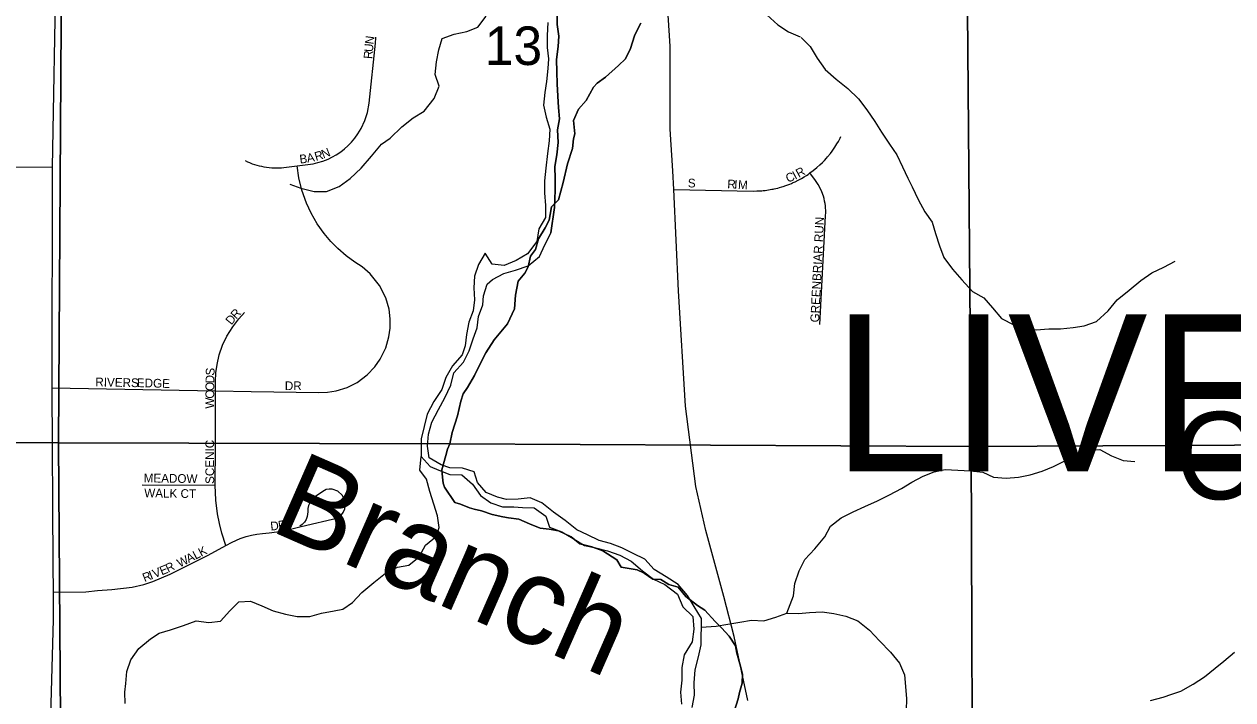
# Model space of a CAD drawing. Extents: x 1985906 to 2277390, y 930619 to 1324581.
# Drawn here: x 2123724 to 2130652, y 1175711 to 1179583 of the extents above; entities that cross this region are included whole.
import ezdxf

# ---------------------------------------------------------------- set-up
doc = ezdxf.new("R2010")
doc.units = 0
for name, color, linetype in [('GM_X_County_Road', 7, 'Continuous'), ('GM_X_Major_River', 7, 'Continuous'), ('GM_X_Major_River_Text', 7, 'Continuous'), ('GM_X_Minor_River', 7, 'Continuous'), ('GM_X_Minor_River_Text', 7, 'Continuous'), ('GM_X_Section', 7, 'Continuous'), ('GM_X_Section_Text', 7, 'Continuous'), ('GM_X_State_Route', 7, 'Continuous'), ('GM_X_Township_Subdivision', 7, 'Continuous'), ('GM_X_Township_Subdivision_Text', 7, 'Continuous'), ('GM_X_Township_Text', 7, 'Continuous')]:
    doc.layers.add(name, color=color, linetype=linetype)

msp = doc.modelspace()

# ---------------------------------------------------------------- linework, layer by layer
at = {"layer": 'GM_X_County_Road'}
msp.add_lwpolyline([(2123773.2, 1166122.9), (2123795.2, 1166134.3), (2123816, 1166178.8), (2123824.9, 1166242.7), (2123823.4, 1166364.4), (2123796, 1168158.8), (2123801.3, 1169024), (2123808.5, 1169900.6), (2123825, 1171925.5), (2123846.5, 1174524.1), (2123892.6, 1176168.6), (2123891.6, 1176327.9), (2123890.5, 1176487.3), (2123883.7, 1177498.1), (2123886.6, 1178763.4), (2123908.1, 1179926.8)], dxfattribs=at)
at = {"layer": 'GM_X_Major_River'}
for points in [[(2126707.7, 1178319.1), (2126742.1, 1178387.2), (2126762.9, 1178531.7), (2126767.4, 1178632.1), (2126767.7, 1178696.4), (2126766, 1178766.7), (2126776.4, 1178835), (2126784.8, 1178905.2), (2126781.1, 1178977.6), (2126791.5, 1179039.8), (2126785.8, 1179106.1), (2126782.1, 1179170.4), (2126778.4, 1179240.7), (2126776.8, 1179309.1), (2126775.1, 1179381.4), (2126785.7, 1179454.5), (2126787.8, 1179513.9), (2126778.1, 1179580.2), (2126778.4, 1179648.5)], [(2126778.4, 1179648.5), (2126778.1, 1179580.2), (2126787.8, 1179513.9), (2126785.7, 1179454.5), (2126775.1, 1179381.4), (2126776.8, 1179309.1), (2126778.4, 1179240.7), (2126782.1, 1179170.4), (2126785.8, 1179106.1), (2126791.5, 1179039.8), (2126781.1, 1178977.6), (2126784.8, 1178905.2), (2126776.4, 1178835), (2126766, 1178766.7), (2126767.7, 1178696.4), (2126767.4, 1178632.1), (2126762.9, 1178531.7), (2126742.1, 1178387.2), (2126707.7, 1178319.1)], [(2126726, 1179592.6), (2126721.6, 1179518.3), (2126721.3, 1179450), (2126729, 1179383.6), (2126724.7, 1179329.4), (2126718.3, 1179255.1), (2126708, 1179190.9), (2126701.6, 1179118.6), (2126715.3, 1179050.2), (2126737, 1178981.8), (2126732.7, 1178913.5), (2126724.3, 1178841.3), (2126713.9, 1178757), (2126705.5, 1178684.7), (2126707.1, 1178616.4), (2126712.8, 1178544), (2126712.5, 1178475.7), (2126674, 1178409.6), (2126661.6, 1178337.4), (2126609.1, 1178267.4), (2126544.8, 1178229.6), (2126474.4, 1178199.8), (2126406.3, 1178208.2), (2126366.5, 1178270.7), (2126328.1, 1178206.6), (2126305.7, 1178138.4), (2126301.3, 1178072.2), (2126305, 1178003.9), (2126296.6, 1177939.6), (2126272.3, 1177875.5), (2126259.9, 1177805.2), (2126251.5, 1177739), (2126235.2, 1177688.8), (2126178.8, 1177624.9), (2126140.3, 1177558.8), (2126117.9, 1177488.6), (2126071.4, 1177420.6), (2126033, 1177348.4), (2126016.6, 1177278.2), (2126000.2, 1177206), (2125999.7, 1177105.6), (2126051.5, 1177049), (2126101.6, 1177026.6), (2126163.6, 1177002.2), (2126231.8, 1176999.8), (2126293.7, 1176947.3), (2126339.5, 1176882.7), (2126399.5, 1176840.2), (2126465.6, 1176817.8), (2126529.7, 1176817.4), (2126579.9, 1176813.1), (2126648, 1176810.7), (2126714, 1176764.2), (2126735.7, 1176699.8), (2126805.8, 1176673.3), (2126869.8, 1176634.8), (2126935.8, 1176596.2), (2126999.9, 1176581.8), (2127068, 1176565.4), (2127138, 1176540.9), (2127204.1, 1176506.4), (2127268, 1176449.8), (2127331.9, 1176403.2), (2127395.9, 1176372.7), (2127467.9, 1176316.1), (2127499.6, 1176243.6), (2127557.5, 1176189.1), (2127563.1, 1176116.7), (2127552.7, 1176044.4), (2127506.2, 1175968.4), (2127493.8, 1175896.1), (2127493.5, 1175823.8), (2127485.1, 1175755.5), (2127490.8, 1175687.2)], [(2127552.9, 1175666.8), (2127565.3, 1175737), (2127563.6, 1175809.3), (2127570, 1175883.6), (2127588.4, 1175957.9), (2127604.8, 1176026.1), (2127605.5, 1176176.7), (2127563.8, 1176245.3), (2127526, 1176309.8), (2127472.1, 1176372.3), (2127404.2, 1176416.9), (2127334.2, 1176457.4), (2127282.3, 1176518), (2127214.3, 1176550.5), (2127150.3, 1176583), (2127084.2, 1176607.5), (2127020.1, 1176623.9), (2126952.1, 1176656.4), (2126892.1, 1176684.9), (2126824.2, 1176739.5), (2126758.2, 1176786), (2126690.3, 1176840.6), (2126624.3, 1176869.1), (2126556, 1176861.5), (2126487.8, 1176859.8), (2126437.7, 1176872.1), (2126371.7, 1176898.6), (2126321.8, 1176957.1), (2126304.1, 1177017.5), (2126236, 1177038), (2126163.8, 1177040.4), (2126113.8, 1177058.7), (2126045.8, 1177097.3), (2126036.1, 1177165.6), (2126042.4, 1177233.9), (2126060.8, 1177302.1), (2126099.3, 1177374.2), (2126135.7, 1177442.3), (2126170.2, 1177514.4), (2126186.6, 1177584.6), (2126243, 1177646.6), (2126275.4, 1177710.7), (2126297.9, 1177778.9), (2126320.2, 1177843.1), (2126328.6, 1177907.3), (2126353, 1177975.5), (2126357.2, 1178025.7), (2126377.6, 1178093.9), (2126407.8, 1178119.8), (2126474.2, 1178153.6), (2126540.5, 1178173.3), (2126612.8, 1178199), (2126677.2, 1178250.9), (2126707.7, 1178319.1)]]:
    msp.add_lwpolyline(points, dxfattribs=at)
at = {"layer": 'GM_X_Minor_River'}
for points in [[(2126803.6, 1180178.9), (2126859.4, 1180192.5), (2126931.6, 1180190.1), (2126995.7, 1180181.7), (2127063.9, 1180181.3), (2127124, 1180179), (2127192.2, 1180180.6), (2127254.5, 1180190.3), (2127326.7, 1180194), (2127398.9, 1180195.6), (2127469.1, 1180189.2), (2127531, 1180152.7), (2127595, 1180098.1), (2127624.7, 1180029.6), (2127658.5, 1179961.1), (2127698.2, 1179890.6), (2127744, 1179828.1), (2127789.8, 1179763.5), (2127851.8, 1179725), (2127917.8, 1179686.5), (2127981.7, 1179635.9), (2128043.6, 1179579.3), (2128105.6, 1179538.8), (2128171.7, 1179510.3)], [(2125247.3, 1178666.5), (2125309.4, 1178644.1), (2125385.5, 1178623.6), (2125457.7, 1178623.2), (2125530.1, 1178652.9), (2125592.5, 1178698.8), (2125654.9, 1178758.7), (2125715.4, 1178826.7), (2125771.9, 1178894.7), (2125822.2, 1178930.6), (2125888.7, 1178994.5), (2125953.2, 1179046.4), (2126017.5, 1179084.2), (2126074.1, 1179156.2), (2126102.5, 1179228.3), (2126078.8, 1179294.8), (2126087.1, 1179367.1), (2126101.5, 1179435.3), (2126119.9, 1179501.5), (2126188.2, 1179525.2), (2126260.5, 1179540.9), (2126324.8, 1179566.6), (2126371.2, 1179628.7)], [(2128177.6, 1179506.3), (2128229.5, 1179455.8), (2128269.3, 1179387.3), (2128315.1, 1179322.7), (2128379, 1179268.1), (2128444.9, 1179213.5), (2128506.8, 1179154.9), (2128554.6, 1179092.4), (2128600.4, 1179025.8), (2128638.2, 1178963.4), (2128684, 1178894.8), (2128725.8, 1178834.3), (2128757.6, 1178765.8), (2128789.4, 1178701.4), (2128813.2, 1178651), (2128848.9, 1178578.5), (2128886.7, 1178508), (2128928.5, 1178447.5), (2128948.2, 1178383.1), (2128969.9, 1178312.7), (2128995.7, 1178246.3), (2129045.5, 1178179.7), (2129099.3, 1178117.1), (2129159.2, 1178050.5), (2129225.2, 1178014), (2129275, 1177957.4), (2129326.9, 1177896.9), (2129396.9, 1177860.4), (2129461, 1177839.9), (2129525.1, 1177831.5), (2129597.3, 1177837.2), (2129663.5, 1177836.8), (2129735.8, 1177844.4), (2129800, 1177854.1), (2129870.3, 1177879.8), (2129936.8, 1177939.8), (2129989.3, 1178003.7), (2130057.7, 1178059.6), (2130124.2, 1178113.5), (2130188.6, 1178157.3), (2130256.9, 1178191.1), (2130321.3, 1178224.9)], [(2128094.9, 1176208.6), (2128133.7, 1176306.4), (2128142, 1176378.7), (2128166.5, 1176450.9), (2128198.9, 1176515), (2128255.3, 1176576.9), (2128313.8, 1176644.9), (2128346.2, 1176707), (2128406.6, 1176754.9), (2128475, 1176788.7), (2128543.3, 1176818.4), (2128615.7, 1176852.2), (2128684.1, 1176886), (2128752.4, 1176921.8), (2128812.8, 1176957.6), (2128877.1, 1176993.4), (2128939.4, 1177017.1), (2129003.7, 1177030.9), (2129075.9, 1177026.4), (2129148, 1177024), (2129218.2, 1177015.6), (2129280.2, 1176987.1), (2129352.4, 1176980.7), (2129422.6, 1176986.4), (2129490.9, 1177000.1), (2129559.2, 1177021.8), (2129623.5, 1177047.5), (2129685.8, 1177079.3), (2129754.2, 1177115.1), (2129816.5, 1177142.9), (2129888.7, 1177146.5), (2129956.7, 1177110), (2130022.8, 1177083.5), (2130090.9, 1177077.1)], [(2124302, 1175690.5), (2124300.3, 1175754.8), (2124306.6, 1175805), (2124312.9, 1175873.2), (2124335.3, 1175939.4), (2124381.8, 1176005.4), (2124448.2, 1176061.3), (2124498.5, 1176093.2), (2124562.8, 1176112.9), (2124637.1, 1176136.6), (2124709.5, 1176164.4), (2124781.6, 1176153.9), (2124849.8, 1176161.6), (2124902.3, 1176221.6), (2124954.7, 1176273.5), (2125020.9, 1176277.2), (2125086.9, 1176250.7), (2125151, 1176220.2), (2125221.1, 1176201.8), (2125289.2, 1176189.4), (2125361.4, 1176189), (2125427.7, 1176208.7), (2125499.9, 1176220.4), (2125550.1, 1176230.1), (2125606.5, 1176268), (2125658.9, 1176326), (2125727.4, 1176383.8), (2125795.8, 1176437.7), (2125864.2, 1176471.5), (2125928.4, 1176483.2), (2125988.8, 1176531.1), (2126025.2, 1176597.2), (2126087.7, 1176649.1), (2126102, 1176699.2), (2126092.3, 1176765.6), (2126072.5, 1176832), (2126048.8, 1176904.4), (2126029.1, 1176974.8), (2125991.3, 1177027.3), (2125999.7, 1177106)], [(2127605.1, 1176127.1), (2127689.6, 1176134.1), (2127757.8, 1176143.8), (2127826.1, 1176155.4), (2127892.3, 1176167.1), (2127964.5, 1176164.7), (2128032.8, 1176184.4), (2128095.1, 1176208.2), (2128163.2, 1176205.8), (2128225.4, 1176211.5), (2128297.7, 1176215.1), (2128365.8, 1176206.7), (2128433.9, 1176190.3), (2128502, 1176163.8), (2128569.9, 1176111.2), (2128625.7, 1176048.6), (2128689.6, 1175984), (2128741.4, 1175921.4), (2128769.2, 1175855), (2128780.5, 1175718.3), (2128780.2, 1175650)], [(2130180.4, 1175706.6), (2130252.7, 1175726.3), (2130302.9, 1175744.1), (2130353.1, 1175759.9), (2130425.5, 1175801.6), (2130489.9, 1175843.5), (2130550.3, 1175893.4), (2130600.7, 1175933.3), (2130661.1, 1175985.2)]]:
    msp.add_lwpolyline(points, dxfattribs=at)
at = {"layer": 'GM_X_Section'}
for points in [[(2121489, 1179863.7), (2123937.9, 1179887.9), (2123921.1, 1177184.6), (2121517.5, 1177191.9)], [(2131769.6, 1179897.5), (2131794.5, 1177176.4), (2129152.7, 1177162.1), (2129130.1, 1179887.9)], [(2121517.5, 1177191.9), (2123921.1, 1177184.6), (2123939.7, 1174541.2), (2121557.9, 1174530.8)], [(2131794.5, 1177176.4), (2131809.9, 1174520.2), (2129161.9, 1174511.4), (2129152.7, 1177162.1)]]:
    msp.add_lwpolyline(points, close=True, dxfattribs=at)
for points in [[(2127258, 1179588.6), (2127227.5, 1179530.2), (2127222.2, 1179515.3), (2127200.1, 1179443.4), (2127170.9, 1179383.7), (2127130.5, 1179345.5), (2127056.4, 1179279.9), (2127007.8, 1179245.6), (2126987.7, 1179222.4), (2126945.1, 1179146.4), (2126902.1, 1179095.9), (2126873.1, 1179030.8), (2126880.9, 1178955.2), (2126873.2, 1178925.4), (2126867.1, 1178870), (2126838.3, 1178783.2), (2126813.9, 1178674.9), (2126786.7, 1178576), (2126746.3, 1178536.4), (2126738.8, 1178493.1), (2126732.4, 1178460.6), (2126709.8, 1178415.8), (2126671.2, 1178351.9), (2126654.3, 1178292.3), (2126626.2, 1178252.8), (2126613.4, 1178191.9), (2126593.5, 1178155.2), (2126554.6, 1178110.2), (2126540.7, 1178030.4), (2126535, 1177952), (2126493.9, 1177865.1), (2126417.4, 1177773.8), (2126370.7, 1177699), (2126333.5, 1177629.7), (2126304.4, 1177570), (2126264.4, 1177500.7), (2126240.4, 1177465.3), (2126226, 1177422), (2126208, 1177339.4), (2126178, 1177243.1), (2126163.4, 1177177.8), (2123921.1, 1177184.6), (2123937.9, 1179887.9)], [(2129130.1, 1179887.9), (2129152.7, 1177162.1), (2126163.4, 1177177.8), (2126178, 1177243.1), (2126208, 1177339.4), (2126226, 1177422), (2126240.4, 1177465.3), (2126264.4, 1177500.7), (2126304.4, 1177570), (2126333.5, 1177629.7), (2126370.7, 1177699), (2126417.4, 1177773.8), (2126493.9, 1177865.1), (2126535, 1177952), (2126540.7, 1178030.4), (2126554.6, 1178110.2), (2126593.5, 1178155.2), (2126613.4, 1178191.9), (2126626.2, 1178252.8), (2126654.3, 1178292.3), (2126671.2, 1178351.9), (2126709.8, 1178415.8), (2126732.4, 1178460.6), (2126738.8, 1178493.1), (2126746.3, 1178536.4), (2126786.7, 1178576), (2126813.9, 1178674.9), (2126838.3, 1178783.2), (2126867.1, 1178870), (2126873.2, 1178925.4), (2126880.9, 1178955.2), (2126873.1, 1179030.8), (2126902.1, 1179095.9), (2126945.1, 1179146.4), (2126987.7, 1179222.4), (2127007.8, 1179245.6), (2127056.4, 1179279.9), (2127130.5, 1179345.5), (2127170.9, 1179383.7), (2127200.1, 1179443.4), (2127222.2, 1179515.3), (2127227.5, 1179530.2), (2127258, 1179588.6)], [(2123939.7, 1174541.2), (2123921.1, 1177184.6), (2126163.4, 1177177.8), (2126150.7, 1177146.9), (2126140.3, 1177110.4), (2126118.3, 1177029.1), (2126121.6, 1176987.2), (2126124.8, 1176952.1), (2126133.3, 1176929.2), (2126193.2, 1176842), (2126224.7, 1176832.9), (2126276.8, 1176811.8), (2126302.9, 1176803.9), (2126345.3, 1176794.9), (2126405.6, 1176773.9), (2126467.1, 1176759.6), (2126500, 1176753.2), (2126558.7, 1176747.1), (2126620.5, 1176719.3), (2126682.2, 1176694.3), (2126734.1, 1176689.4), (2126786.1, 1176680.4), (2126858.8, 1176646), (2126909.9, 1176604.7), (2126978.3, 1176587.8), (2127041.4, 1176564.1), (2127121.2, 1176513.5), (2127145, 1176471.9), (2127238, 1176455.3), (2127277.8, 1176436.8), (2127327.4, 1176402.1), (2127372.4, 1176399.9), (2127419.2, 1176372), (2127472.6, 1176356.3), (2127515.6, 1176304), (2127583.2, 1176252), (2127624.5, 1176224.1), (2127684.1, 1176159.8), (2127721.4, 1176123.7), (2127764.3, 1176076.8), (2127800.6, 1176020.4), (2127808, 1175978.6), (2127825.2, 1175916.7), (2127841.1, 1175857.4), (2127839.1, 1175806), (2127824.8, 1175753.2), (2127817.1, 1175716.6), (2127781.8, 1175608.2)], [(2127781.8, 1175608.2), (2127817.1, 1175716.6), (2127824.8, 1175753.2), (2127839.1, 1175806), (2127841.1, 1175857.4), (2127825.2, 1175916.7), (2127808, 1175978.6), (2127800.6, 1176020.4), (2127764.3, 1176076.8), (2127721.4, 1176123.7), (2127684.1, 1176159.8), (2127624.5, 1176224.1), (2127583.2, 1176252), (2127515.6, 1176304), (2127472.6, 1176356.3), (2127419.2, 1176372), (2127372.4, 1176399.9), (2127327.4, 1176402.1), (2127277.8, 1176436.8), (2127238, 1176455.3), (2127145, 1176471.9), (2127121.2, 1176513.5), (2127041.4, 1176564.1), (2126978.3, 1176587.8), (2126909.9, 1176604.7), (2126858.8, 1176646), (2126786.1, 1176680.4), (2126734.1, 1176689.4), (2126682.2, 1176694.3), (2126620.5, 1176719.3), (2126558.7, 1176747.1), (2126500, 1176753.2), (2126467.1, 1176759.6), (2126405.6, 1176773.9), (2126345.3, 1176794.9), (2126302.9, 1176803.9), (2126276.8, 1176811.8), (2126224.7, 1176832.9), (2126193.2, 1176842), (2126133.3, 1176929.2), (2126124.8, 1176952.1), (2126121.6, 1176987.2), (2126118.3, 1177029.1), (2126140.3, 1177110.4), (2126150.7, 1177146.9), (2126163.4, 1177177.8), (2129152.7, 1177162.1), (2129161.9, 1174511.4)]]:
    msp.add_lwpolyline(points, dxfattribs=at)
at = {"layer": 'GM_X_State_Route'}
for points in [[(2127427, 1179017.2), (2127425.9, 1179457.3), (2127402.1, 1179847.1), (2127393.8, 1179933)], [(2127872.4, 1175706.4), (2127793.9, 1176073.6), (2127734.2, 1176302.4), (2127631.6, 1176681.6), (2127573.8, 1176934.4), (2127514.7, 1177394.2), (2127474.5, 1178055.1), (2127447.1, 1178635), (2127442.1, 1178742), (2127427.1, 1178980.7), (2127427, 1179017.2)]]:
    msp.add_lwpolyline(points, dxfattribs=at)
at = {"layer": 'GM_X_Township_Subdivision'}
for points in [[(2124990.8, 1178800.9), (2125003.7, 1178794.8), (2125016, 1178789.5), (2125031.6, 1178783.4), (2125044.9, 1178778.9), (2125057.4, 1178775), (2125070.7, 1178771.4), (2125083.9, 1178768.3), (2125097.9, 1178765.6), (2125113.4, 1178763.1), (2125128.3, 1178761.4), (2125143.2, 1178760.1), (2125161, 1178759.4), (2125181.5, 1178759.6), (2125198.3, 1178760.5), (2125212.4, 1178761.8), (2125287.8, 1178771.1), (2125350.4, 1178778.7), (2125379.8, 1178783.3), (2125407.2, 1178789.6), (2125436.4, 1178798.6), (2125465.5, 1178810.1), (2125490.5, 1178822.2), (2125512, 1178834.5), (2125538.3, 1178852), (2125559.5, 1178868.4), (2125578.5, 1178885.2), (2125599.7, 1178906.8), (2125619.5, 1178930.4), (2125637.3, 1178955.2), (2125654.9, 1178984.3), (2125676.2, 1179030.1), (2125691.4, 1179077.1), (2125701.1, 1179129.5), (2125737.4, 1179474.5), (2125738.2, 1179482.9), (2125739.2, 1179495.9), (2125739.7, 1179508.5)], [(2127447.1, 1178635), (2127903.3, 1178626.9), (2127923.7, 1178627.2), (2127945.5, 1178628.3), (2127952.5, 1178628.8), (2127960.4, 1178629.5), (2127971.7, 1178630.7), (2127981.7, 1178632), (2127990.1, 1178633.2), (2127999.4, 1178634.7), (2128010.1, 1178636.7), (2128017.8, 1178638.2), (2128022.9, 1178639.2), (2128032.8, 1178641.5), (2128043, 1178644), (2128053.7, 1178646.8), (2128066.6, 1178650.5), (2128074.8, 1178653.1), (2128088.9, 1178657.8), (2128101.9, 1178662.6), (2128112.4, 1178666.7), (2128121.3, 1178670.3), (2128127.8, 1178673.1), (2128132.3, 1178675.1), (2128143.4, 1178680.2), (2128160.7, 1178688.8), (2128179.9, 1178699.3), (2128195.3, 1178708.5), (2128207.6, 1178716.2), (2128216.9, 1178722.4), (2128227.9, 1178730.2), (2128247.3, 1178744.5), (2128267.4, 1178760.8), (2128284.5, 1178776), (2128300.1, 1178791), (2128310.9, 1178802.1), (2128322.6, 1178814.9), (2128329.4, 1178822.7), (2128345.4, 1178842.3), (2128355.6, 1178855.9), (2128370.6, 1178877.5), (2128382.4, 1178896.3), (2128391, 1178911.1), (2128401.2, 1178930.1), (2128405.9, 1178939.5)], [(2123088.6, 1178766.3), (2123886.6, 1178763.4)], [(2123883.7, 1177498.1), (2124820.5, 1177481.8), (2125025.5, 1177478.2), (2125412.4, 1177471.5), (2125462.8, 1177473.3), (2125512.4, 1177481.5), (2125575.6, 1177501.6), (2125631.8, 1177530.3), (2125690.1, 1177573.8), (2125733.6, 1177619.6), (2125764.9, 1177664), (2125796.3, 1177728.1), (2125814.7, 1177791.3), (2125821.7, 1177841.4), (2125822.1, 1177894.9), (2125815.1, 1177949.5), (2125796.2, 1178014.6), (2125760.9, 1178085.1), (2125707.4, 1178152.4), (2125660.9, 1178192.8), (2125619, 1178219.9), (2125570.1, 1178255.3), (2125521.9, 1178296.7), (2125481.7, 1178337.3), (2125443.5, 1178382.5), (2125404, 1178437.9), (2125368, 1178500.1), (2125341.5, 1178557.2), (2125315.1, 1178631.7), (2125297.8, 1178702.6), (2125287.8, 1178771.1)], [(2128284.7, 1177862.6), (2128317.5, 1178485.1), (2128318.3, 1178503), (2128318.3, 1178515.2), (2128317.5, 1178530.5), (2128316.4, 1178542.4), (2128314.7, 1178554.9), (2128312.1, 1178568.9), (2128308.8, 1178583.2), (2128304.9, 1178597.1), (2128295.5, 1178623), (2128284.6, 1178646.4), (2128274.8, 1178663.9), (2128259.9, 1178686.2), (2128227.9, 1178730.2)], [(2124879.3, 1176595.1), (2124856.7, 1176666.7), (2124842.9, 1176722), (2124832.2, 1176777.9), (2124822.8, 1176855.8), (2124819.6, 1176940.8), (2124820.5, 1177160.8), (2124820.5, 1177481.8), (2124820.5, 1177536.8), (2124822.8, 1177585.4), (2124829.3, 1177633.5), (2124842.3, 1177688.7), (2124861.6, 1177744), (2124885.6, 1177794.9), (2124919, 1177849.4), (2124953.8, 1177894.2), (2124987.4, 1177929.9)], [(2124400.1, 1176942.6), (2124819.6, 1176940.8)], [(2123891.6, 1176327.9), (2124077.9, 1176330.8), (2124144.7, 1176337.3), (2124226.9, 1176343.6), (2124343.5, 1176357.3), (2124409, 1176372.5), (2124461.8, 1176389.1), (2124561.3, 1176431.9), (2124678.3, 1176490.2), (2124779, 1176540.5), (2124879.3, 1176595.1), (2124915.5, 1176614.8), (2124961.9, 1176635), (2124996.5, 1176646.6), (2125026, 1176654.3), (2125058, 1176660.6), (2125090.9, 1176664.8), (2125127.6, 1176668.3), (2125172.9, 1176673), (2125220, 1176681.8), (2125250, 1176689), (2125287.9, 1176697.9), (2125311.9, 1176703.6), (2125524.4, 1176754), (2125543.2, 1176770.5), (2125553, 1176784.3), (2125561.7, 1176805.3), (2125564.9, 1176831.2), (2125560.1, 1176858.3), (2125547, 1176883.1), (2125521.4, 1176906.3), (2125490.1, 1176917.9), (2125471.2, 1176919.1), (2125454.2, 1176916.8), (2125436.2, 1176905), (2125394, 1176877.2), (2125379, 1176865), (2125368.7, 1176853.3), (2125362.9, 1176844.4), (2125355.7, 1176829.5), (2125354, 1176824.9), (2125350.1, 1176808.1), (2125349.2, 1176788.4), (2125346.7, 1176762.1), (2125340.3, 1176744.3), (2125331.3, 1176729.7), (2125317.6, 1176715.1), (2125304.3, 1176705.7)]]:
    msp.add_lwpolyline(points, dxfattribs=at)

# ---------------------------------------------------------------- texts
at = {"layer": 'GM_X_Major_River_Text'}
msp.add_text('Branch', height=500.23, rotation=336.34351, dxfattribs=at).set_placement((2125121.8, 1176685.3))
at = {"layer": 'GM_X_Minor_River_Text'}
msp.add_text('Cossett', height=500.24, rotation=4.18791, dxfattribs=at).set_placement((2130338.4, 1176842.5))
at = {"layer": 'GM_X_Section_Text'}
msp.add_text('13', height=221, rotation=0.00001, dxfattribs=at).set_placement((2126364.3, 1179348.9))
at = {"layer": 'GM_X_Township_Subdivision_Text'}
for s, rotation, p in [('N', 82.3057, (2125726, 1179464.9)), ('U', 85.25087, (2125722.4, 1179421.7)), ('R', 85.25854, (2125719.1, 1179382.2)), ('B', 6.93826, (2125305.1, 1178783.8)), ('A', 10.89119, (2125348.1, 1178789.2)), ('R', 16.75488, (2125396.7, 1178798.8)), ('N', 22.00204, (2125439.3, 1178811.9)), ('I', 27.54253, (2128143.4, 1178690.9)), ('R', 28.60996, (2128163.8, 1178701.5)), ('S', 0.00001, (2127528.1, 1178647.4)), ('R', 356.76899, (2127753.1, 1178643)), ('I', 356.76442, (2127792.6, 1178640.8)), ('M', 356.75163, (2127814.6, 1178639.5)), ('C', 20.62426, (2128100.3, 1178674.2)), ('GREENBRIAR RUN', 87.18423, (2128279.9, 1177872.9)), ('D', 50.74288, (2124911.5, 1177856.2)), ('R', 47.6626, (2124938.9, 1177889.7)), ('D', 89.77872, (2124813.3, 1177524.7)), ('S', 85.78782, (2124813.4, 1177567.8)), ('RIVERS', 358.8315, (2124131.5, 1177507.8)), ('EDGE', 358.44674, (2124369.2, 1177503.4)), ('O', 89.78139, (2124813.1, 1177480.8)), ('DR', 0.00001, (2125218.1, 1177485.8)), ('O', 89.77872, (2124812.9, 1177436.8)), ('W', 89.78143, (2124812.7, 1177379.6)), ('SCENIC', 90, (2124812.7, 1176948.4)), ('MEADOW', 359.10531, (2124408.7, 1176957.8)), ('WALK CT', 359.09112, (2124411.7, 1176871.8)), ('D', 6.61535, (2125137.9, 1176680.6)), ('R', 7.92852, (2125182.9, 1176685.8)), ('K', 27.69366, (2124738.3, 1176530.1)), ('W', 26.67784, (2124615.5, 1176468.5)), ('A', 26.65301, (2124666.6, 1176494.1)), ('L', 26.6628, (2124706, 1176513.9)), ('V', 21.57414, (2124471.2, 1176407.8)), ('E', 21.86829, (2124512.4, 1176424.1)), ('R', 26.5108, (2124549, 1176439)), ('R', 21.56238, (2124413.9, 1176385.2)), ('I', 21.59679, (2124450.7, 1176399.7))]:
    msp.add_text(s, height=50, rotation=rotation, dxfattribs=at).set_placement(p)
at = {"layer": 'GM_X_Township_Text'}
msp.add_text('LIVERPOOL', height=900, rotation=0.00001, dxfattribs=at).set_placement((2128357.7, 1177020.9))

doc.saveas('drawing.dxf')
